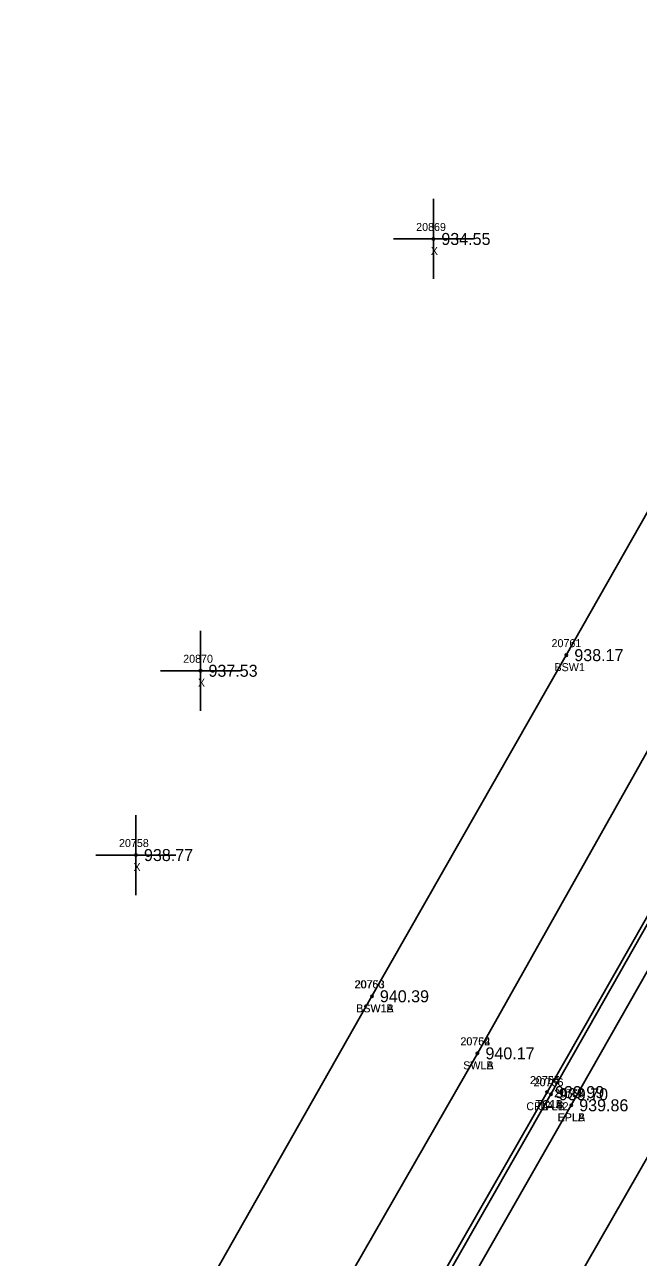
# Model space of a CAD drawing. Extents: x 1576181 to 1577685, y 1099396 to 1101490.
# Drawn here: x 1576572.3 to 1576648.9, y 1099972.4 to 1100126.4 of the extents above; entities that cross this region are included whole.
import ezdxf

# ---------------------------------------------------------------- set-up
doc = ezdxf.new("R2010")
doc.units = 0
for name, color, linetype in [('RD_DTM_BkLn1', 7, 'Continuous'), ('RD_DTM_BkLn2', 7, 'Continuous'), ('RD_EX_Conc', 7, 'Continuous'), ('RD_EX_Conc_txCode', 7, 'Continuous'), ('RD_EX_Misc', 7, 'Continuous'), ('RD_EX_Misc_txCode', 7, 'Continuous'), ('RD_EX_Road', 7, 'Continuous'), ('RD_EX_Road_txCode', 7, 'Continuous'), ('RD_EX_TX_Conc_ELEV', 7, 'Continuous'), ('RD_EX_TX_Misc_ELEV', 7, 'Continuous'), ('RD_EX_TX_Road_ELEV', 7, 'Continuous'), ('RD_SMD_Locator', 7, 'Continuous')]:
    doc.layers.add(name, color=color, linetype=linetype)

msp = doc.modelspace()

# ---------------------------------------------------------------- linework, layer by layer
at = {"layer": 'RD_DTM_BkLn1'}
msp.add_lwpolyline([(1576435.96, 1099635.47), (1576469.98, 1099685.91), (1576496.51, 1099728.46), (1576522.67, 1099770.85), (1576549.06, 1099813.4), (1576563.36, 1099837.2), (1576575.09, 1099855.95), (1576600.75, 1099898.96), (1576625.57, 1099942.14), (1576652.37, 1099988.91), (1576675.03, 1100029.12), (1576699.51, 1100072.44), (1576723.52, 1100115.7), (1576748.08, 1100158.53), (1576774.13, 1100203.85), (1576797.97, 1100246.52), (1576822.46, 1100289.82), (1576846.93, 1100333.35), (1576871.37, 1100376.46), (1576888.27, 1100406.22)], dxfattribs=at)
at = {"layer": 'RD_DTM_BkLn2'}
msp.add_lwpolyline([(1576569.71, 1099889.13), (1576574.56, 1099891.34), (1576579.27, 1099894.47), (1576584.19, 1099899.55), (1576592.25, 1099913.59), (1576612.84, 1099949.87), (1576637.54, 1099993.05), (1576637.54, 1099993.05), (1576662.19, 1100036.34), (1576686.67, 1100079.69), (1576711.46, 1100123.12), (1576735.92, 1100166.59), (1576760.76, 1100210.19), (1576785.21, 1100253.55), (1576809.13, 1100296.43), (1576833.85, 1100340.61), (1576852.06, 1100373.52), (1576858.66, 1100385.37)], dxfattribs=at)
at = {"layer": 'RD_EX_Conc'}
for points in [[(1576537.53, 1099904.47), (1576543.86, 1099909.52), (1576562.16, 1099910.99), (1576591.51, 1099962.44), (1576615.66, 1100005.02), (1576615.66, 1100005.02), (1576639.95, 1100047.65), (1576665.61, 1100092.87), (1576689.57, 1100135.17), (1576714.68, 1100179.66), (1576738.99, 1100222.53), (1576763.6, 1100265.87), (1576774.84, 1100284.48), (1576788.69, 1100308.17), (1576806.14, 1100353.34), (1576815.02, 1100384.28), (1576820.35, 1100399.92), (1576825.22, 1100406.93), (1576832.15, 1100418.17), (1576835.04, 1100423.11), (1576847.13, 1100416.35), (1576868.44, 1100408.23), (1576872.09, 1100412.69)], [(1576592.25, 1099913.59), (1576580.2, 1099912.49), (1576604.17, 1099954.86), (1576628.85, 1099997.89), (1576628.85, 1099997.89), (1576652.81, 1100040.47), (1576678.28, 1100085.17), (1576702.19, 1100127.32), (1576727.43, 1100172.04), (1576752.1, 1100215.39), (1576776.49, 1100258.76), (1576788, 1100277.34), (1576801.96, 1100301.42), (1576820.18, 1100348.3), (1576829.19, 1100379.59), (1576833.87, 1100393.41), (1576838.32, 1100402.43), (1576861.82, 1100391.11)], [(1576569.87, 1099888.69), (1576574.84, 1099890.86), (1576574.84, 1099890.86), (1576579.65, 1099894.15), (1576584.72, 1099899.29), (1576592.68, 1099913.3), (1576613.45, 1099949.72), (1576638.02, 1099992.78), (1576638.02, 1099992.78), (1576662.6, 1100036.05), (1576687.14, 1100079.44), (1576711.91, 1100122.93), (1576736.42, 1100166.35), (1576761.24, 1100209.96), (1576785.67, 1100253.17), (1576809.57, 1100296.25), (1576834.31, 1100340.56), (1576852.46, 1100373.22), (1576852.46, 1100373.22), (1576859.24, 1100385.1)]]:
    msp.add_lwpolyline(points, dxfattribs=at)
at = {"layer": 'RD_EX_Misc'}
for p, q in [((1576623.34, 1100094.66), (1576623.34, 1100104.66)), ((1576618.34, 1100099.66), (1576628.34, 1100099.66)), ((1576594.25, 1100040.7), (1576594.25, 1100050.7)), ((1576589.25, 1100045.7), (1576599.25, 1100045.7)), ((1576586.19, 1100017.67), (1576586.19, 1100027.67)), ((1576581.19, 1100022.67), (1576591.19, 1100022.67))]:
    msp.add_line(p, q, dxfattribs=at)
at = {"layer": 'RD_EX_Road'}
msp.add_lwpolyline([(1576574.84, 1099890.86), (1576581.17, 1099887.16), (1576595.39, 1099911.97), (1576615.87, 1099948.17), (1576640.56, 1099991.4), (1576640.56, 1099991.4), (1576664.88, 1100034.19), (1576689.84, 1100078.06), (1576714.22, 1100121.19), (1576739.08, 1100164.66), (1576764.15, 1100209.11), (1576788.31, 1100251.8), (1576812.15, 1100294.46), (1576837.06, 1100339.37), (1576855.38, 1100371.53), (1576853.98, 1100372.48), (1576862.98, 1100388.86), (1576865.16, 1100391.95), (1576873.15, 1100402.8), (1576877.45, 1100410.32)], dxfattribs=at)
at = {"layer": 'RD_SMD_Locator'}
for centre in [(1576623.34, 1100099.66), (1576639.95, 1100047.65), (1576594.25, 1100045.7), (1576586.19, 1100022.67), (1576615.66, 1100005.02), (1576615.66, 1100005.02), (1576628.85, 1099997.89), (1576628.85, 1099997.89), (1576637.54, 1099993.05), (1576637.54, 1099993.05), (1576638.02, 1099992.78), (1576638.02, 1099992.78), (1576640.56, 1099991.4), (1576640.56, 1099991.4)]:
    msp.add_circle(centre, 0.15, dxfattribs=at)

# ---------------------------------------------------------------- texts
at = {"layer": 'RD_EX_Conc_txCode'}
for s, p in [('20761', (1576638.1, 1100048.65)), ('BSW1', (1576638.47, 1100045.65)), ('20760', (1576613.48, 1100006.02)), ('20753', (1576613.54, 1100006.02)), ('BSW1A', (1576613.69, 1100003.02)), ('BSW1B', (1576613.71, 1100003.02)), ('20762', (1576626.71, 1099998.89)), ('20754', (1576626.73, 1099998.89)), ('SWLA', (1576627.07, 1099995.89)), ('SWLB', (1576627.08, 1099995.89)), ('20764', (1576635.4, 1099994.05)), ('20755', (1576635.42, 1099994.05)), ('20766', (1576635.86, 1099993.78)), ('20756', (1576635.88, 1099993.78)), ('CFLA 42', (1576634.95, 1099990.78)), ('TC1A', (1576636.09, 1099991.05)), ('TC1B', (1576636.11, 1099991.05)), ('CFLB', (1576636.35, 1099990.78))]:
    msp.add_text(s, height=1, dxfattribs=at).set_placement(p)
at = {"layer": 'RD_EX_Misc_txCode'}
for s, p in [('20869', (1576621.19, 1100100.66)), ('X', (1576623.02, 1100097.66)), ('20870', (1576592.09, 1100046.7)), ('X', (1576593.93, 1100043.7)), ('20758', (1576584.07, 1100023.67)), ('X', (1576585.88, 1100020.67))]:
    msp.add_text(s, height=1, dxfattribs=at).set_placement(p)
at = {"layer": 'RD_EX_Road_txCode'}
for s, p in [('20768', (1576638.42, 1099992.4)), ('20757', (1576638.44, 1099992.4)), ('EPLA', (1576638.86, 1099989.4)), ('EPLB', (1576638.88, 1099989.4))]:
    msp.add_text(s, height=1, dxfattribs=at).set_placement(p)
at = {"layer": 'RD_EX_TX_Conc_ELEV'}
for s, p in [('938.17', (1576640.95, 1100046.9)), ('940.39', (1576616.66, 1100004.27)), ('940.39', (1576616.66, 1100004.27)), ('940.17', (1576629.85, 1099997.14)), ('940.17', (1576629.85, 1099997.14)), ('939.99', (1576638.54, 1099992.3)), ('939.99', (1576638.54, 1099992.3)), ('939.70', (1576639.02, 1099992.03)), ('939.70', (1576639.02, 1099992.03))]:
    msp.add_text(s, height=1.5, dxfattribs=at).set_placement(p)
at = {"layer": 'RD_EX_TX_Misc_ELEV'}
for s, p in [('934.55', (1576624.34, 1100098.91)), ('937.53', (1576595.25, 1100044.95)), ('938.77', (1576587.19, 1100021.92))]:
    msp.add_text(s, height=1.5, dxfattribs=at).set_placement(p)
at = {"layer": 'RD_EX_TX_Road_ELEV'}
msp.add_text('939.86', height=1.5, dxfattribs=at).set_placement((1576641.56, 1099990.65))
msp.add_text('939.86', height=1.5, dxfattribs=at).set_placement((1576641.56, 1099990.65))

doc.saveas('drawing.dxf')
